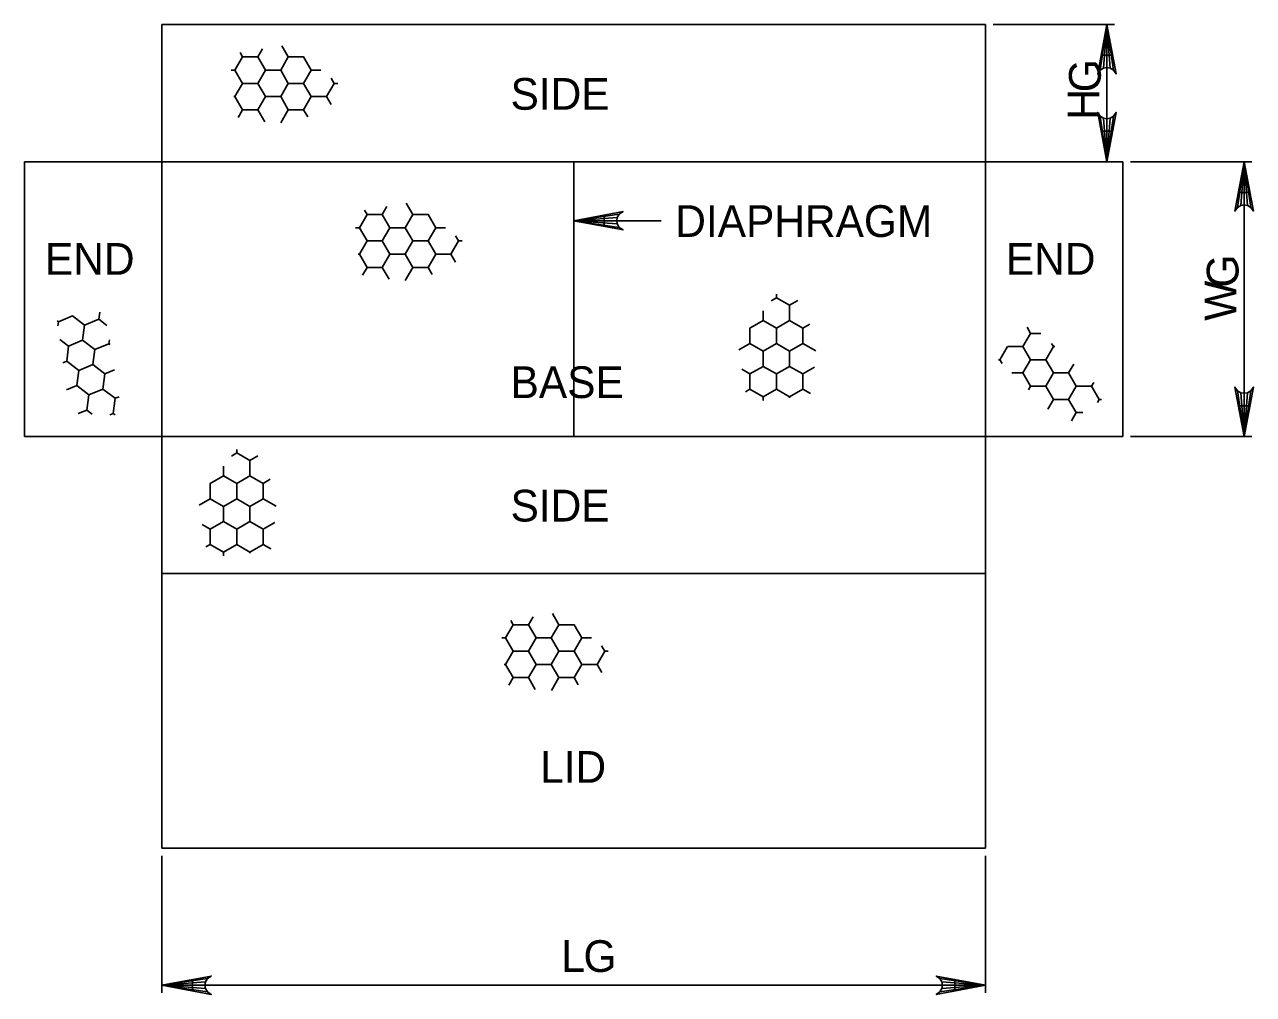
# Model space of a CAD drawing. Extents: x 638142 to 639291, y 297247 to 298438.
# Drawn here: x 638714.4 to 638830.5, y 297439 to 297530.7 of the extents above; entities that cross this region are included whole.
import ezdxf

# ---------------------------------------------------------------- set-up
doc = ezdxf.new("R2010")
doc.units = 0
doc.layers.add('3', color=7, linetype='Continuous')
doc.layers.add('5', color=7, linetype='Continuous')

msp = doc.modelspace()

# ---------------------------------------------------------------- linework, layer by layer
at = {"layer": '3'}
for p, q in [((638727.34, 297530.67), (638727.34, 297452.81)), ((638805.2, 297530.67), (638727.34, 297530.67)), ((638805.2, 297452.81), (638805.2, 297530.67)), ((638739.29, 297527.61), (638738.68, 297528.67)), ((638734.25, 297526.36), (638734.97, 297527.61)), ((638734.97, 297527.61), (638734.73, 297528.02)), ((638734.97, 297527.61), (638736.41, 297527.61)), ((638736.41, 297527.61), (638736.85, 297528.37)), ((638737.13, 297526.36), (638736.41, 297527.61)), ((638738.57, 297526.36), (638739.29, 297527.61)), ((638739.29, 297527.61), (638740.73, 297527.61)), ((638740.73, 297527.61), (638740.76, 297527.65)), ((638741.46, 297526.36), (638740.73, 297527.61)), ((638733.89, 297526.36), (638734.25, 297526.36)), ((638734.97, 297525.11), (638734.25, 297526.36)), ((638736.41, 297525.11), (638737.13, 297526.36)), ((638737.13, 297526.36), (638738.57, 297526.36)), ((638739.29, 297525.11), (638738.57, 297526.36)), ((638740.73, 297525.11), (638741.46, 297526.36)), ((638741.46, 297526.36), (638742.38, 297526.36)), ((638734.25, 297523.86), (638734.97, 297525.11)), ((638734.97, 297525.11), (638736.41, 297525.11)), ((638737.13, 297523.86), (638736.41, 297525.11)), ((638738.57, 297523.86), (638739.29, 297525.11)), ((638739.29, 297525.11), (638740.73, 297525.11)), ((638741.46, 297523.86), (638740.73, 297525.11)), ((638742.9, 297523.86), (638743.62, 297525.11)), ((638743.62, 297525.11), (638743.33, 297525.6)), ((638743.62, 297525.11), (638743.96, 297525.11)), ((638734.14, 297523.86), (638734.25, 297523.86)), ((638734.97, 297522.62), (638734.25, 297523.86)), ((638736.41, 297522.62), (638737.13, 297523.86)), ((638737.13, 297523.86), (638738.57, 297523.86)), ((638739.29, 297522.62), (638738.57, 297523.86)), ((638740.73, 297522.62), (638741.46, 297523.86)), ((638741.46, 297523.86), (638742.9, 297523.86)), ((638743.34, 297523.1), (638742.9, 297523.86)), ((638734.55, 297521.89), (638734.97, 297522.62)), ((638734.97, 297522.62), (638736.41, 297522.62)), ((638737.06, 297521.49), (638736.41, 297522.62)), ((638738.58, 297521.38), (638739.29, 297522.62)), ((638739.29, 297522.62), (638740.73, 297522.62)), ((638741.13, 297521.94), (638740.73, 297522.62)), ((638714.36, 297517.7), (638714.36, 297491.74)), ((638714.36, 297517.7), (638818.17, 297517.7)), ((638766.27, 297517.7), (638766.27, 297491.74)), ((638818.17, 297491.74), (638818.17, 297517.7)), ((638751.05, 297512.71), (638750.44, 297513.78)), ((638746.01, 297511.46), (638746.73, 297512.71)), ((638746.73, 297512.71), (638746.49, 297513.12)), ((638746.73, 297512.71), (638748.17, 297512.71)), ((638748.17, 297512.71), (638748.61, 297513.47)), ((638748.89, 297511.46), (638748.17, 297512.71)), ((638750.33, 297511.46), (638751.05, 297512.71)), ((638751.05, 297512.71), (638752.5, 297512.71)), ((638752.5, 297512.71), (638752.52, 297512.75)), ((638753.22, 297511.46), (638752.5, 297512.71)), ((638745.65, 297511.46), (638746.01, 297511.46)), ((638746.73, 297510.21), (638746.01, 297511.46)), ((638748.17, 297510.21), (638748.89, 297511.46)), ((638748.89, 297511.46), (638750.33, 297511.46)), ((638751.05, 297510.21), (638750.33, 297511.46)), ((638752.5, 297510.21), (638753.22, 297511.46)), ((638753.22, 297511.46), (638754.14, 297511.46)), ((638746.01, 297508.97), (638746.73, 297510.21)), ((638746.73, 297510.21), (638748.17, 297510.21)), ((638748.89, 297508.97), (638748.17, 297510.21)), ((638750.33, 297508.97), (638751.05, 297510.21)), ((638751.05, 297510.21), (638752.5, 297510.21)), ((638753.22, 297508.97), (638752.5, 297510.21)), ((638754.66, 297508.97), (638755.38, 297510.21)), ((638755.38, 297510.21), (638755.1, 297510.71)), ((638755.38, 297510.21), (638755.72, 297510.21)), ((638745.9, 297508.97), (638746.01, 297508.97)), ((638746.73, 297507.72), (638746.01, 297508.97)), ((638748.17, 297507.72), (638748.89, 297508.97)), ((638748.89, 297508.97), (638750.33, 297508.97)), ((638751.05, 297507.72), (638750.33, 297508.97)), ((638752.5, 297507.72), (638753.22, 297508.97)), ((638753.22, 297508.97), (638754.66, 297508.97)), ((638755.1, 297508.2), (638754.66, 297508.97)), ((638746.31, 297506.99), (638746.73, 297507.72)), ((638746.73, 297507.72), (638748.17, 297507.72)), ((638748.82, 297506.6), (638748.17, 297507.72)), ((638750.34, 297506.49), (638751.05, 297507.72)), ((638751.05, 297507.72), (638752.5, 297507.72)), ((638752.89, 297507.04), (638752.5, 297507.72)), ((638785.43, 297504.85), (638784.93, 297504.56)), ((638785.43, 297504.85), (638785.43, 297505.19)), ((638786.67, 297504.13), (638785.43, 297504.85)), ((638787.44, 297504.57), (638786.67, 297504.13)), ((638717.57, 297502.58), (638718.89, 297503.13)), ((638718.9, 297503.13), (638720.04, 297502.26)), ((638721.37, 297502.81), (638721.46, 297503.47)), ((638784.18, 297502.68), (638784.18, 297503.61)), ((638786.67, 297502.68), (638786.67, 297504.13)), ((638717.45, 297502.66), (638717.57, 297502.58)), ((638717.52, 297502.19), (638717.57, 297502.58)), ((638719.85, 297500.83), (638720.04, 297502.26)), ((638720.04, 297502.26), (638721.37, 297502.81)), ((638721.37, 297502.81), (638722.14, 297502.22)), ((638782.93, 297501.96), (638782.89, 297501.99)), ((638784.18, 297502.68), (638782.93, 297501.96)), ((638782.93, 297500.52), (638782.93, 297501.96)), ((638785.43, 297501.96), (638784.18, 297502.68)), ((638786.67, 297502.68), (638785.43, 297501.96)), ((638785.43, 297500.52), (638785.43, 297501.96)), ((638787.92, 297501.96), (638786.67, 297502.68)), ((638788.6, 297502.35), (638787.92, 297501.96)), ((638787.92, 297500.52), (638787.92, 297501.96)), ((638809.45, 297501.47), (638809.12, 297502.05)), ((638717.69, 297500.91), (638718.52, 297500.27)), ((638718.52, 297500.27), (638719.85, 297500.83)), ((638719.85, 297500.83), (638721, 297499.95)), ((638722.33, 297500.5), (638722.38, 297500.85)), ((638808.73, 297500.22), (638809.45, 297501.47)), ((638809.45, 297501.47), (638810.42, 297501.47)), ((638718.34, 297498.84), (638718.52, 297500.27)), ((638720.81, 297498.52), (638721, 297499.95)), ((638721, 297499.95), (638722.33, 297500.5)), ((638722.33, 297500.5), (638722.45, 297500.41)), ((638782.93, 297500.52), (638781.87, 297499.91)), ((638784.18, 297499.8), (638782.93, 297500.52)), ((638785.43, 297500.52), (638784.18, 297499.8)), ((638784.18, 297498.36), (638784.18, 297499.8)), ((638786.67, 297499.8), (638785.43, 297500.52)), ((638787.92, 297500.52), (638786.67, 297499.8)), ((638786.67, 297498.36), (638786.67, 297499.8)), ((638789.16, 297499.81), (638787.92, 297500.52)), ((638806.56, 297498.98), (638807.28, 297500.22)), ((638807.29, 297500.22), (638808.73, 297500.22)), ((638809.45, 297498.98), (638808.73, 297500.22)), ((638810.89, 297498.98), (638811.61, 297500.22)), ((638811.61, 297500.22), (638811.44, 297500.53)), ((638811.61, 297500.22), (638811.76, 297500.22)), ((638717.98, 297498.69), (638718.34, 297498.84)), ((638718.34, 297498.84), (638719.48, 297497.97)), ((638719.48, 297497.97), (638720.81, 297498.52)), ((638720.81, 297498.52), (638721.96, 297497.64)), ((638806.42, 297498.98), (638806.56, 297498.98)), ((638806.76, 297498.64), (638806.56, 297498.98)), ((638808.73, 297497.73), (638809.45, 297498.98)), ((638809.45, 297498.98), (638810.89, 297498.98)), ((638811.61, 297497.73), (638810.89, 297498.98)), ((638813.05, 297497.73), (638813.54, 297498.57)), ((638719.3, 297496.54), (638719.48, 297497.97)), ((638721.77, 297496.21), (638721.96, 297497.64)), ((638721.96, 297497.64), (638722.86, 297498.02)), ((638782.93, 297497.64), (638782.17, 297498.08)), ((638784.18, 297498.36), (638782.93, 297497.64)), ((638782.93, 297496.2), (638782.93, 297497.64)), ((638785.43, 297497.64), (638784.18, 297498.36)), ((638786.67, 297498.36), (638785.43, 297497.64)), ((638785.43, 297496.2), (638785.43, 297497.64)), ((638787.92, 297497.64), (638786.67, 297498.36)), ((638789.04, 297498.28), (638787.92, 297497.64)), ((638787.92, 297496.2), (638787.92, 297497.64)), ((638807.67, 297497.73), (638808.73, 297497.73)), ((638809.45, 297496.48), (638808.73, 297497.73)), ((638810.89, 297496.48), (638811.61, 297497.73)), ((638811.61, 297497.73), (638813.05, 297497.73)), ((638813.77, 297496.48), (638813.05, 297497.73)), ((638718.32, 297496.13), (638719.3, 297496.54)), ((638719.3, 297496.54), (638720.44, 297495.66)), ((638720.44, 297495.66), (638721.77, 297496.21)), ((638721.77, 297496.21), (638722.92, 297495.34)), ((638782.93, 297496.2), (638782.52, 297495.96)), ((638784.18, 297495.48), (638782.93, 297496.2)), ((638785.43, 297496.2), (638784.18, 297495.48)), ((638786.67, 297495.48), (638785.43, 297496.2)), ((638787.92, 297496.2), (638786.67, 297495.48)), ((638788.65, 297495.78), (638787.92, 297496.2)), ((638809.25, 297496.15), (638809.45, 297496.48)), ((638809.45, 297496.48), (638810.89, 297496.48)), ((638811.61, 297495.23), (638810.89, 297496.48)), ((638813.05, 297495.23), (638813.77, 297496.48)), ((638813.77, 297496.48), (638815.22, 297496.48)), ((638815.22, 297496.48), (638815.42, 297496.83)), ((638815.94, 297495.23), (638815.22, 297496.48)), ((638720.25, 297494.23), (638720.44, 297495.66)), ((638722.73, 297493.91), (638722.92, 297495.34)), ((638722.92, 297495.34), (638723.29, 297495.49)), ((638784.18, 297495.12), (638784.18, 297495.48)), ((638786.67, 297495.37), (638786.67, 297495.48)), ((638811.08, 297494.32), (638811.61, 297495.23)), ((638811.61, 297495.23), (638813.05, 297495.23)), ((638813.77, 297493.98), (638813.05, 297495.23)), ((638815.77, 297494.95), (638815.94, 297495.23)), ((638815.94, 297495.23), (638816.17, 297495.23)), ((638719.44, 297493.89), (638720.25, 297494.23)), ((638720.25, 297494.23), (638720.76, 297493.84)), ((638722.43, 297493.78), (638722.73, 297493.91)), ((638722.73, 297493.91), (638722.92, 297493.76)), ((638813.33, 297493.22), (638813.77, 297493.98)), ((638813.77, 297493.98), (638814.41, 297493.98)), ((638714.36, 297491.74), (638818.17, 297491.74)), ((638734.41, 297490.17), (638734.41, 297490.51)), ((638734.41, 297490.17), (638733.92, 297489.88)), ((638735.66, 297489.45), (638734.41, 297490.17)), ((638736.42, 297489.89), (638735.66, 297489.45)), ((638735.66, 297488.01), (638735.66, 297489.45)), ((638733.16, 297488.01), (638731.91, 297487.28)), ((638733.16, 297488.01), (638733.16, 297488.93)), ((638734.41, 297487.28), (638733.16, 297488.01)), ((638735.66, 297488.01), (638734.41, 297487.28)), ((638736.91, 297487.28), (638735.66, 297488.01)), ((638731.91, 297487.28), (638731.87, 297487.31)), ((638731.91, 297485.84), (638731.91, 297487.28)), ((638734.41, 297485.84), (638734.41, 297487.28)), ((638737.58, 297487.68), (638736.91, 297487.28)), ((638736.91, 297485.84), (638736.91, 297487.28)), ((638731.91, 297485.84), (638730.85, 297485.23)), ((638733.16, 297485.12), (638731.91, 297485.84)), ((638734.41, 297485.84), (638733.16, 297485.12)), ((638735.66, 297485.12), (638734.41, 297485.84)), ((638736.91, 297485.84), (638735.66, 297485.12)), ((638738.14, 297485.13), (638736.91, 297485.84)), ((638733.16, 297483.68), (638733.16, 297485.12)), ((638735.66, 297483.68), (638735.66, 297485.12)), ((638731.91, 297482.96), (638731.15, 297483.4)), ((638733.16, 297483.68), (638731.91, 297482.96)), ((638734.41, 297482.96), (638733.16, 297483.68)), ((638735.66, 297483.68), (638734.41, 297482.96)), ((638736.91, 297482.96), (638735.66, 297483.68)), ((638738.03, 297483.6), (638736.91, 297482.96)), ((638731.91, 297481.52), (638731.91, 297482.96)), ((638734.41, 297481.52), (638734.41, 297482.96)), ((638736.91, 297481.52), (638736.91, 297482.96)), ((638731.91, 297481.52), (638731.51, 297481.28)), ((638733.16, 297480.8), (638731.91, 297481.52)), ((638734.41, 297481.52), (638733.16, 297480.8)), ((638735.66, 297480.8), (638734.41, 297481.52)), ((638736.91, 297481.52), (638735.66, 297480.8)), ((638737.63, 297481.1), (638736.91, 297481.52)), ((638733.16, 297480.44), (638733.16, 297480.8)), ((638735.66, 297480.69), (638735.66, 297480.8)), ((638727.34, 297478.77), (638805.2, 297478.77)), ((638760.55, 297473.93), (638760.31, 297474.33)), ((638761.99, 297473.93), (638762.43, 297474.69)), ((638764.87, 297473.93), (638764.26, 297474.99)), ((638759.83, 297472.68), (638760.55, 297473.93)), ((638760.55, 297473.93), (638761.99, 297473.93)), ((638762.71, 297472.68), (638761.99, 297473.93)), ((638764.15, 297472.68), (638764.87, 297473.93)), ((638764.87, 297473.93), (638766.31, 297473.93)), ((638766.31, 297473.93), (638766.34, 297473.96)), ((638767.03, 297472.68), (638766.31, 297473.93)), ((638759.47, 297472.68), (638759.83, 297472.68)), ((638760.55, 297471.43), (638759.83, 297472.68)), ((638761.99, 297471.43), (638762.71, 297472.68)), ((638762.71, 297472.68), (638764.15, 297472.68)), ((638764.87, 297471.43), (638764.15, 297472.68)), ((638766.31, 297471.43), (638767.03, 297472.68)), ((638767.03, 297472.68), (638767.96, 297472.68)), ((638769.2, 297471.43), (638768.91, 297471.92)), ((638759.83, 297470.18), (638760.55, 297471.43)), ((638760.55, 297471.43), (638761.99, 297471.43)), ((638762.71, 297470.18), (638761.99, 297471.43)), ((638764.15, 297470.18), (638764.87, 297471.43)), ((638764.87, 297471.43), (638766.31, 297471.43)), ((638767.03, 297470.18), (638766.31, 297471.43)), ((638768.48, 297470.18), (638769.2, 297471.43)), ((638769.2, 297471.43), (638769.53, 297471.43)), ((638759.71, 297470.18), (638759.83, 297470.18)), ((638760.55, 297468.93), (638759.83, 297470.18)), ((638761.99, 297468.93), (638762.71, 297470.18)), ((638762.71, 297470.18), (638764.15, 297470.18)), ((638764.87, 297468.93), (638764.15, 297470.18)), ((638766.31, 297468.93), (638767.03, 297470.18)), ((638767.03, 297470.18), (638768.48, 297470.18)), ((638768.92, 297469.42), (638768.48, 297470.18)), ((638760.13, 297468.21), (638760.55, 297468.93)), ((638760.55, 297468.93), (638761.99, 297468.93)), ((638762.63, 297467.81), (638761.99, 297468.93)), ((638764.16, 297467.7), (638764.87, 297468.93)), ((638764.87, 297468.93), (638766.31, 297468.93)), ((638766.7, 297468.26), (638766.31, 297468.93)), ((638727.34, 297452.81), (638805.2, 297452.81))]:
    msp.add_line(p, q, dxfattribs=at)
at = {"layer": '5'}
for p, q in [((638805.92, 297530.67), (638817.39, 297530.67)), ((638816.67, 297530.67), (638816.67, 297517.7)), ((638818.89, 297517.7), (638830.37, 297517.7)), ((638829.65, 297517.7), (638829.65, 297491.74)), ((638766.27, 297512.13), (638774.55, 297512.13)), ((638830.37, 297491.74), (638818.89, 297491.74)), ((638727.34, 297452.09), (638727.34, 297439.13)), ((638805.2, 297439.13), (638805.2, 297452.09)), ((638727.34, 297439.85), (638805.2, 297439.85))]:
    msp.add_line(p, q, dxfattribs=at)
for points in [[(638816.67, 297530.67), (638817.54, 297526.01), (638817.29, 297526.37), (638816.98, 297526.55), (638816.67, 297526.61), (638816.36, 297526.55), (638816.04, 297526.37), (638815.8, 297526.01), (638816.67, 297530.67), (638816.04, 297526.37), (638816.36, 297526.55), (638816.67, 297530.67), (638816.67, 297526.61), (638816.98, 297526.55), (638816.67, 297530.67), (638817.29, 297526.37)], [(638816.67, 297517.7), (638815.8, 297522.36), (638816.04, 297522), (638816.36, 297521.81), (638816.67, 297521.76), (638816.98, 297521.81), (638817.29, 297522), (638817.54, 297522.36), (638816.67, 297517.7), (638817.29, 297522), (638816.98, 297521.81), (638816.67, 297517.7), (638816.67, 297521.76), (638816.36, 297521.81), (638816.67, 297517.7), (638816.04, 297522)], [(638829.65, 297517.7), (638830.52, 297513.04), (638830.27, 297513.39), (638829.96, 297513.58), (638829.65, 297513.63), (638829.33, 297513.58), (638829.02, 297513.39), (638828.77, 297513.04), (638829.65, 297517.7), (638829.02, 297513.39), (638829.33, 297513.58), (638829.65, 297517.7), (638829.65, 297513.63), (638829.96, 297513.58), (638829.65, 297517.7), (638830.27, 297513.39)], [(638766.27, 297512.13), (638770.93, 297513), (638770.57, 297512.75), (638770.38, 297512.44), (638770.33, 297512.13), (638770.38, 297511.82), (638770.57, 297511.5), (638770.93, 297511.26), (638766.27, 297512.13), (638770.57, 297511.5), (638770.38, 297511.82), (638766.27, 297512.13), (638770.33, 297512.13), (638770.38, 297512.44), (638766.27, 297512.13), (638770.57, 297512.75)], [(638829.65, 297491.74), (638828.77, 297496.4), (638829.02, 297496.05), (638829.33, 297495.86), (638829.65, 297495.81), (638829.96, 297495.86), (638830.27, 297496.05), (638830.52, 297496.4), (638829.65, 297491.74), (638830.27, 297496.05), (638829.96, 297495.86), (638829.65, 297491.74), (638829.65, 297495.81), (638829.33, 297495.86), (638829.65, 297491.74), (638829.02, 297496.05)], [(638727.34, 297439.85), (638732, 297440.72), (638731.64, 297440.48), (638731.46, 297440.16), (638731.4, 297439.85), (638731.46, 297439.54), (638731.64, 297439.23), (638732, 297438.98), (638727.34, 297439.85), (638731.64, 297439.23), (638731.46, 297439.54), (638727.34, 297439.85), (638731.4, 297439.85), (638731.46, 297440.16), (638727.34, 297439.85), (638731.64, 297440.48)], [(638805.2, 297439.85), (638800.54, 297438.98), (638800.89, 297439.23), (638801.08, 297439.54), (638801.13, 297439.85), (638801.08, 297440.16), (638800.89, 297440.48), (638800.54, 297440.72), (638805.2, 297439.85), (638800.89, 297440.48), (638801.08, 297440.16), (638805.2, 297439.85), (638801.13, 297439.85), (638801.08, 297439.54), (638805.2, 297439.85), (638800.89, 297439.23)]]:
    msp.add_lwpolyline(points, dxfattribs=at)
for points in [[(638816.19, 297527.79), (638817.15, 297527.79), (638816.67, 297530.67)], [(638816.19, 297520.58), (638817.15, 297520.58), (638816.67, 297517.7)], [(638829.17, 297514.81), (638830.13, 297514.81), (638829.65, 297517.7)], [(638769.15, 297511.65), (638769.15, 297512.61), (638766.27, 297512.13)], [(638829.17, 297494.63), (638830.13, 297494.63), (638829.65, 297491.74)], [(638730.22, 297439.37), (638730.22, 297440.33), (638727.34, 297439.85)], [(638802.31, 297439.37), (638802.31, 297440.33), (638805.2, 297439.85)]]:
    msp.add_lwpolyline(points, close=True, dxfattribs=at)

# ---------------------------------------------------------------- texts
for s, p in [('G', (638816.09, 297524.27)), ('H', (638815.95, 297521.68)), ('G', (638829.11, 297505.8)), ('W', (638828.92, 297502.67))]:
    msp.add_text(s, height=3, rotation=90, dxfattribs=at).set_placement(p)
for s, p in [('SIDE', (638760.3, 297522.62)), ('DIAPHRAGM', (638775.87, 297510.59)), ('END', (638716.29, 297507.02)), ('END', (638807.12, 297507.02)), ('BASE', (638760.3, 297495.36)), ('SIDE', (638760.3, 297483.69)), ('LID', (638763.09, 297458.99)), ('L', (638765.1, 297441.11)), ('G', (638767.19, 297441.1))]:
    msp.add_text(s, height=3, dxfattribs=at).set_placement(p)

doc.saveas('drawing.dxf')
